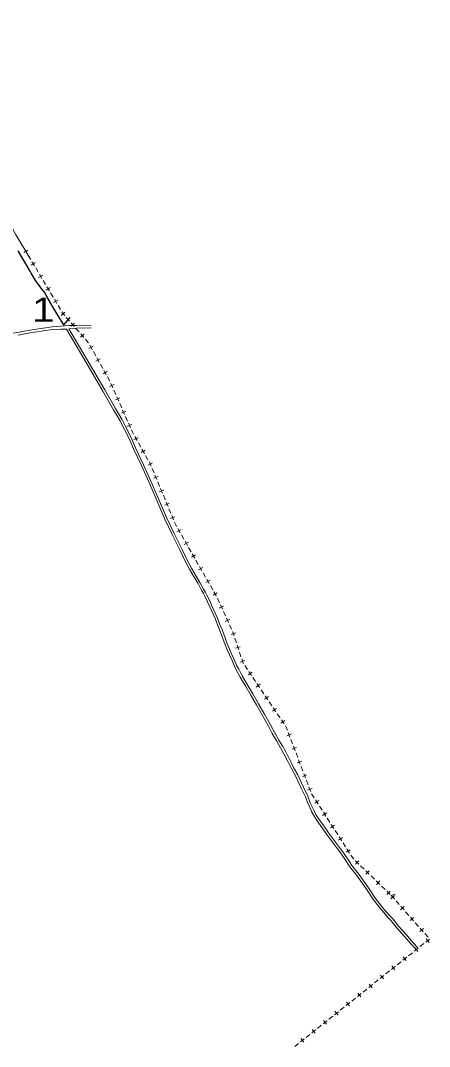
# Model space of a CAD drawing. Extents: x 476989 to 498418, y 4381813 to 4416555.
# Drawn here: x 487660 to 488503, y 4383749 to 4385862 of the extents above; entities that cross this region are included whole.
import ezdxf

# ---------------------------------------------------------------- set-up
doc = ezdxf.new("R2010")
doc.units = 0
doc.header["$LTSCALE"] = 20
for name, color, linetype, lineweight in [('13', 7, 'Continuous', 13), ('34', 7, 'Continuous', 13), ('36', 7, 'Continuous', 13), ('6', 7, 'Continuous', 25)]:
    doc.layers.add(name, color=color, linetype=linetype, lineweight=lineweight)

msp = doc.modelspace()

# ---------------------------------------------------------------- linework, layer by layer
at = {"layer": '34'}
for p, q in [((487660.88, 4385403.79), (487666.01, 4385395.21)), ((487675.43, 4385389.2), (487666.84, 4385384.07)), ((487668.57, 4385390.93), (487673.7, 4385382.34)), ((487676.26, 4385378.05), (487680.1, 4385371.63)), ((487680.1, 4385371.63), (487681.39, 4385369.47)), ((487690.81, 4385363.45), (487682.22, 4385358.33)), ((487683.95, 4385365.18), (487689.08, 4385356.6)), ((487691.65, 4385352.31), (487696.78, 4385343.72)), ((487706.19, 4385337.71), (487697.61, 4385332.58)), ((487699.34, 4385339.44), (487704.47, 4385330.85)), ((487707.03, 4385326.56), (487712.16, 4385317.98)), ((487721.58, 4385311.97), (487712.99, 4385306.84)), ((487714.72, 4385313.69), (487719.85, 4385305.11)), ((487722.41, 4385300.82), (487727.54, 4385292.23)), ((487730.1, 4385287.95), (487735.23, 4385279.37)), ((487736.96, 4385286.22), (487728.38, 4385281.09)), ((487737.8, 4385275.07), (487742.93, 4385266.49)), ((487751.82, 4385261.23), (487744.31, 4385254.62)), ((487754.68, 4385250.42), (487761.29, 4385242.92)), ((487771.65, 4385238.73), (487764.14, 4385232.12)), ((487764.59, 4385239.18), (487771.2, 4385231.68)), ((487774.51, 4385227.92), (487781.12, 4385220.42)), ((487791.48, 4385216.23), (487783.97, 4385209.62)), ((487784.42, 4385216.68), (487791.03, 4385209.18)), ((487809.92, 4385191.44), (487801.18, 4385186.58)), ((487803.12, 4385193.38), (487807.98, 4385184.64)), ((487810.4, 4385180.27), (487815.26, 4385171.53)), ((487824.48, 4385165.23), (487815.74, 4385160.37)), ((487817.68, 4385167.17), (487822.54, 4385158.43)), ((487824.97, 4385154.06), (487829.83, 4385145.31)), ((487832.25, 4385140.95), (487837.11, 4385132.21)), ((487839.05, 4385139.01), (487830.31, 4385134.15)), ((487839.53, 4385127.84), (487844.39, 4385119.1)), ((487853.11, 4385112.03), (487843.96, 4385107.99)), ((487846.51, 4385114.59), (487850.56, 4385105.44)), ((487852.58, 4385100.87), (487856.62, 4385091.72)), ((487865.24, 4385084.61), (487856.09, 4385080.56)), ((487858.64, 4385087.16), (487862.69, 4385078.01)), ((487864.71, 4385073.44), (487868.75, 4385064.29)), ((487877.37, 4385057.18), (487868.22, 4385053.14)), ((487870.77, 4385059.73), (487874.82, 4385050.59)), ((487876.84, 4385046.01), (487880.89, 4385036.87)), ((487889.5, 4385029.75), (487880.35, 4385025.71)), ((487882.9, 4385032.3), (487886.95, 4385023.16)), ((487902.68, 4385003.38), (487893.96, 4384998.49)), ((487895.88, 4385005.3), (487900.77, 4384996.58)), ((487903.21, 4384992.21), (487908.1, 4384983.49)), ((487917.35, 4384977.22), (487908.63, 4384972.33)), ((487910.54, 4384979.14), (487915.43, 4384970.42)), ((487917.88, 4384966.06), (487922.77, 4384957.33)), ((487932.01, 4384951.06), (487923.29, 4384946.17)), ((487931.57, 4384939.42), (487935.41, 4384930.19)), ((487943.86, 4384922.89), (487934.63, 4384919.04)), ((487937.33, 4384925.58), (487941.17, 4384916.35)), ((487943.09, 4384911.73), (487946.93, 4384902.5)), ((487955.38, 4384895.2), (487946.15, 4384891.35)), ((487948.85, 4384897.89), (487952.69, 4384888.66)), ((487954.61, 4384884.04), (487958.45, 4384874.81)), ((487966.9, 4384867.51), (487957.67, 4384863.66)), ((487960.36, 4384870.2), (487964.2, 4384860.97)), ((487966.13, 4384856.35), (487969.97, 4384847.12)), ((487978.42, 4384839.82), (487969.19, 4384835.98)), ((487971.88, 4384842.51), (487975.72, 4384833.28)), ((487991.22, 4384813.46), (487982.54, 4384808.49)), ((487984.4, 4384815.31), (487989.37, 4384806.63)), ((487991.85, 4384802.3), (487996.82, 4384793.62)), ((488006.12, 4384787.43), (487997.44, 4384782.46)), ((487999.3, 4384789.29), (488004.27, 4384780.61)), ((488006.75, 4384776.27), (488011.72, 4384767.59)), ((488021.02, 4384761.4), (488012.34, 4384756.44)), ((488014.2, 4384763.26), (488019.16, 4384754.58)), ((488021.65, 4384750.24), (488026.62, 4384741.56)), ((488035.92, 4384735.38), (488027.24, 4384730.41)), ((488029.1, 4384737.23), (488034.06, 4384728.55)), ((488036.55, 4384724.21), (488041.52, 4384715.53)), ((488050.82, 4384709.35), (488042.14, 4384704.38)), ((488043.99, 4384711.2), (488048.96, 4384702.52)), ((488051.45, 4384698.19), (488056.41, 4384689.51)), ((488065.72, 4384683.32), (488057.04, 4384678.35)), ((488065.82, 4384671.89), (488070, 4384662.8)), ((488078.72, 4384655.82), (488069.64, 4384651.64)), ((488072.09, 4384658.27), (488076.27, 4384649.19)), ((488078.36, 4384644.65), (488082.54, 4384635.56)), ((488091.26, 4384628.58), (488082.18, 4384624.4)), ((488084.63, 4384631.03), (488088.81, 4384621.95)), ((488090.91, 4384617.4), (488095.09, 4384608.32)), ((488103.7, 4384600.68), (488094.19, 4384597.56)), ((488102.06, 4384589.62), (488105.18, 4384580.12)), ((488113.05, 4384572.18), (488103.54, 4384569.07)), ((488106.74, 4384575.38), (488109.85, 4384565.88)), ((488111.41, 4384561.12), (488114.53, 4384551.62)), ((488122.4, 4384543.69), (488112.89, 4384540.57)), ((488122.17, 4384533.32), (488127.77, 4384525.04)), ((488137.51, 4384519.57), (488129.23, 4384513.96)), ((488130.57, 4384520.91), (488136.18, 4384512.62)), ((488138.98, 4384508.48), (488144.59, 4384500.2)), ((488154.33, 4384494.73), (488146.05, 4384489.13)), ((488147.38, 4384496.07), (488152.99, 4384487.79)), ((488155.79, 4384483.65), (488161.4, 4384475.37)), ((488171.14, 4384469.9), (488162.86, 4384464.29)), ((488164.19, 4384471.24), (488169.8, 4384462.95)), ((488172.6, 4384458.81), (488178.21, 4384450.53)), ((488187.95, 4384445.06), (488179.67, 4384439.46)), ((488181.01, 4384446.4), (488186.61, 4384438.12)), ((488189.41, 4384433.98), (488195.02, 4384425.7)), ((488197.82, 4384421.57), (488203.42, 4384413.28)), ((488204.76, 4384420.23), (488196.48, 4384414.62)), ((488218.3, 4384392.39), (488208.96, 4384388.83)), ((488211.85, 4384395.28), (488215.41, 4384385.94)), ((488217.19, 4384381.27), (488220.76, 4384371.92)), ((488228.99, 4384364.37), (488219.64, 4384360.81)), ((488222.53, 4384367.26), (488226.1, 4384357.92)), ((488227.88, 4384353.25), (488231.44, 4384343.9)), ((488239.67, 4384336.35), (488230.33, 4384332.79)), ((488233.22, 4384339.24), (488236.78, 4384329.9)), ((488238.56, 4384325.22), (488242.12, 4384315.88)), ((488250.36, 4384308.33), (488241.01, 4384304.76)), ((488243.9, 4384311.22), (488247.47, 4384301.87)), ((488249.25, 4384297.2), (488252.81, 4384287.86)), ((488261.04, 4384280.31), (488251.7, 4384276.74)), ((488254.59, 4384283.2), (488258.15, 4384273.85)), ((488274.9, 4384255.04), (488266.48, 4384249.64)), ((488267.99, 4384256.55), (488273.39, 4384248.13)), ((488276.09, 4384243.92), (488281.5, 4384235.51)), ((488284.19, 4384231.31), (488289.59, 4384222.89)), ((488291.1, 4384229.8), (488282.68, 4384224.4)), ((488292.29, 4384218.68), (488297.69, 4384210.27)), ((488307.3, 4384204.56), (488298.88, 4384199.16)), ((488300.39, 4384206.07), (488305.79, 4384197.65)), ((488308.49, 4384193.44), (488313.89, 4384185.03)), ((488323.5, 4384179.32), (488315.08, 4384173.92)), ((488316.59, 4384180.83), (488321.99, 4384172.41)), ((488324.69, 4384168.21), (488330.09, 4384159.79)), ((488339.69, 4384154.08), (488331.28, 4384148.68)), ((488332.79, 4384155.59), (488338.19, 4384147.17)), ((488349.98, 4384131.17), (488353.26, 4384128.02)), ((488353.89, 4384128.02), (488350.12, 4384124.1)), ((488353.26, 4384128.02), (488357.19, 4384124.24)), ((488357.05, 4384131.31), (488353.89, 4384128.02)), ((488360.79, 4384120.77), (488368, 4384113.84)), ((488371.6, 4384110.38), (488378.81, 4384103.45)), ((488378.67, 4384110.52), (488371.74, 4384103.32)), ((488382.41, 4384099.99), (488389.62, 4384093.06)), ((488393.22, 4384089.6), (488400.43, 4384082.67)), ((488400.29, 4384089.74), (488393.36, 4384082.53)), ((488404.03, 4384079.2), (488411.24, 4384072.27)), ((488414.84, 4384068.81), (488422.04, 4384061.88)), ((488421.9, 4384068.95), (488414.97, 4384061.74)), ((488432.07, 4384062.39), (488424, 4384060)), ((488431.05, 4384059.55), (488423.53, 4384052.95)), ((488424, 4384060), (488430.59, 4384052.49)), ((488433.89, 4384048.73), (488440.49, 4384041.22)), ((488450.83, 4384037.01), (488443.32, 4384030.41)), ((488443.78, 4384037.47), (488450.37, 4384029.95)), ((488453.67, 4384026.2), (488460.27, 4384018.68)), ((488470.62, 4384014.47), (488463.1, 4384007.87)), ((488463.56, 4384014.93), (488470.16, 4384007.41)), ((488473.46, 4384003.66), (488480.05, 4383996.14)), ((488490.4, 4383991.93), (488482.89, 4383985.34)), ((488483.35, 4383992.39), (488489.94, 4383984.88)), ((488493.24, 4383981.12), (488499.84, 4383973.6)), ((488491.12, 4383960.53), (488483.3, 4383954.3)), ((488502.85, 4383969.88), (488495.03, 4383963.65)), ((488502.05, 4383962.85), (488495.82, 4383970.67)), ((488467.66, 4383941.84), (488459.84, 4383935.61)), ((488479.39, 4383951.19), (488471.57, 4383944.95)), ((488478.6, 4383944.16), (488472.37, 4383951.98)), ((488432.49, 4383913.8), (488424.67, 4383907.57)), ((488431.69, 4383906.78), (488425.46, 4383914.6)), ((488444.21, 4383923.15), (488436.39, 4383916.91)), ((488455.94, 4383932.5), (488448.12, 4383926.26)), ((488455.15, 4383925.47), (488448.91, 4383933.29)), ((488409.04, 4383895.11), (488401.22, 4383888.88)), ((488408.24, 4383888.09), (488402.01, 4383895.91)), ((488420.76, 4383904.46), (488412.94, 4383898.22)), ((488385.58, 4383876.42), (488377.76, 4383870.19)), ((488384.79, 4383869.39), (488378.56, 4383877.21)), ((488397.31, 4383885.76), (488389.48, 4383879.53)), ((488362.13, 4383857.73), (488354.31, 4383851.5)), ((488361.34, 4383850.7), (488355.1, 4383858.52)), ((488373.85, 4383867.07), (488366.03, 4383860.84)), ((488326.95, 4383829.69), (488319.13, 4383823.46)), ((488338.68, 4383839.04), (488330.86, 4383832.81)), ((488337.88, 4383832.01), (488331.65, 4383839.83)), ((488350.4, 4383848.38), (488342.58, 4383842.15)), ((488303.49, 4383811), (488295.67, 4383804.77)), ((488315.22, 4383820.35), (488307.4, 4383814.11)), ((488314.43, 4383813.32), (488308.2, 4383821.14)), ((488280.04, 4383792.31), (488272.22, 4383786.07)), ((488291.77, 4383801.66), (488283.95, 4383795.42)), ((488290.98, 4383794.63), (488284.75, 4383802.45)), ((488256.59, 4383773.62), (488248.77, 4383767.38)), ((488268.32, 4383782.96), (488260.5, 4383776.73)), ((488267.52, 4383775.94), (488261.29, 4383783.76)), ((488233.14, 4383754.92), (488225.32, 4383748.69)), ((488244.87, 4383764.27), (488237.05, 4383758.04)), ((488244.07, 4383757.25), (488237.84, 4383765.07))]:
    msp.add_line(p, q, dxfattribs=at)
for points in [[(487280.6, 4386441.97), (487080, 4386339), (487267, 4386051), (487354, 4385933), (487441, 4385795), (487598, 4385523), (487650, 4385422), (487680.1, 4385371.64)], [(487745.49, 4385262.21), (487748, 4385258), (487751.37, 4385254.17)], [(487794.34, 4385205.43), (487800, 4385199), (487800.7, 4385197.75)], [(487888.97, 4385018.59), (487891, 4385014), (487893.44, 4385009.65)], [(487925.21, 4384952.98), (487928, 4384948), (487929.65, 4384944.04)], [(487977.64, 4384828.66), (487980, 4384823), (487981.92, 4384819.64)], [(488058.89, 4384685.18), (488063, 4384678), (488063.72, 4384676.43)], [(488097.18, 4384603.79), (488098, 4384602), (488100.5, 4384594.37)], [(488116.09, 4384546.88), (488119, 4384538), (488119.37, 4384537.46)], [(488206.23, 4384409.14), (488207, 4384408), (488210.07, 4384399.95)], [(488259.93, 4384269.18), (488260, 4384269), (488265.3, 4384260.75)], [(488340.89, 4384142.97), (488346, 4384135), (488346.38, 4384134.63)]]:
    msp.add_lwpolyline(points, dxfattribs=at)
at = {"layer": '36'}
for p, q in [((487679.81, 4385224.07), (487679.85, 4385224.08)), ((487679.8, 4385218.38), (487679.84, 4385218.39)), ((488332.78, 4384128.05), (488333.4, 4384127.12)), ((488338.74, 4384128.04), (488339.36, 4384127.11))]:
    msp.add_line(p, q, dxfattribs=at)
for points in [[(487497.15, 4385199.42), (487509.69, 4385199.56), (487530.73, 4385201.64), (487543.2, 4385202.51), (487556.97, 4385203.85), (487571.79, 4385206.52), (487597.97, 4385211.35), (487621.23, 4385214.93), (487654.34, 4385219.7), (487679.81, 4385224.07)], [(487679.84, 4385218.39), (487689.06, 4385219.97), (487725.96, 4385225.31), (487743.45, 4385226.24), (487754.77, 4385226.5)], [(487679.85, 4385224.08), (487688.19, 4385225.51), (487725.41, 4385230.89), (487751.05, 4385232.88)], [(487751.51, 4385233.11), (487760.04, 4385233.57), (487775.61, 4385233.93), (487805.83, 4385234.71)], [(487754.77, 4385226.5), (487795.93, 4385157.57), (487829.92, 4385098.83), (487852.21, 4385060.31)], [(487760.04, 4385226.64), (487775.98, 4385228.34), (487805.98, 4385229.09)], [(487760.04, 4385226.64), (487799.89, 4385159.9), (487833.9, 4385101.14), (487856.19, 4385062.62)], [(487655.21, 4385214.16), (487679.8, 4385218.38)], [(487852.21, 4385060.31), (487865.52, 4385037.09), (487871.17, 4385026.06), (487877.83, 4385013.17), (487885.41, 4384997.67), (487892.78, 4384980.04), (487909.58, 4384945.08), (487927.48, 4384905.25), (487957.67, 4384834.81), (487972.51, 4384803.57), (487989.09, 4384770.37), (488000.47, 4384746.72), (488008.53, 4384731.68), (488017.92, 4384715.2), (488026.08, 4384702.24), (488033.4, 4384688.72), (488037.26, 4384681.81), (488039.95, 4384676.45), (488045.87, 4384664.41), (488050.54, 4384654.49), (488054.62, 4384645.57), (488057.39, 4384639.08), (488062.05, 4384628.97), (488066.76, 4384615.91), (488071.16, 4384605.55), (488074.65, 4384596.59), (488077, 4384588.77)], [(487856.19, 4385062.62), (487869.5, 4385039.41), (487875.26, 4385028.16), (487881.94, 4385015.24), (487889.6, 4384999.57), (487896.98, 4384981.93), (487913.76, 4384947.02), (487931.69, 4384907.09), (487961.86, 4384836.7), (487976.64, 4384805.58), (487993.22, 4384772.4), (488004.57, 4384748.81), (488012.55, 4384733.91), (488021.87, 4384717.57), (488030.06, 4384704.56), (488037.43, 4384690.93), (488041.33, 4384683.96), (488044.07, 4384678.49), (488050.02, 4384666.41), (488054.72, 4384656.43), (488058.83, 4384647.43), (488061.6, 4384640.95), (488066.31, 4384630.72), (488071.05, 4384617.59), (488075.42, 4384607.28), (488078.92, 4384598.31), (488081.65, 4384590.5)], [(488081.65, 4384590.5), (488086.37, 4384577.81), (488090.65, 4384567.62), (488095.25, 4384557.47), (488100.6, 4384545.98), (488105.56, 4384534.32), (488109.92, 4384525.64), (488117.24, 4384512.11), (488128.55, 4384492.58), (488139.09, 4384474.89), (488150.57, 4384454.8), (488162.92, 4384432.9), (488175.67, 4384411.04), (488183.45, 4384396.02), (488192.62, 4384379.97), (488200.42, 4384366.3), (488207.44, 4384354.1), (488214.28, 4384340.4), (488219.04, 4384330.9), (488222.99, 4384323.32), (488231.38, 4384308.11), (488243.29, 4384283.17), (488252.18, 4384264.54), (488257.14, 4384250.9), (488261.27, 4384242.16), (488265.21, 4384233.89), (488268.91, 4384226.73), (488275.32, 4384216.42), (488285.7, 4384202.17), (488294.93, 4384189.09), (488309.18, 4384169.66), (488325.75, 4384147.54), (488338.74, 4384128.04)], [(488077, 4384588.77), (488081.75, 4384575.98), (488086.1, 4384565.63), (488090.74, 4384555.4), (488096.06, 4384543.96), (488101.05, 4384532.24), (488105.52, 4384523.34), (488112.91, 4384509.68), (488124.28, 4384490.07), (488134.8, 4384472.39), (488146.25, 4384452.35), (488158.62, 4384430.43), (488171.32, 4384408.65), (488179.09, 4384393.64), (488188.32, 4384377.51), (488196.12, 4384363.84), (488203.07, 4384351.75), (488209.85, 4384338.18), (488214.63, 4384328.65), (488218.61, 4384320.97), (488226.97, 4384305.84), (488238.81, 4384281.03), (488247.6, 4384262.62), (488252.55, 4384248.99), (488256.79, 4384240.03), (488260.77, 4384231.68), (488264.59, 4384224.27), (488271.21, 4384213.65), (488281.67, 4384199.28), (488290.9, 4384186.19), (488305.19, 4384166.71), (488321.7, 4384144.67), (488332.78, 4384128.05)], [(488333.4, 4384127.12), (488338.92, 4384118.84), (488353.38, 4384100.94), (488373.15, 4384072.85), (488387.79, 4384050.88), (488400.24, 4384034.62), (488409.33, 4384023.73), (488416.52, 4384015.35), (488424.19, 4384007.74), (488435.14, 4383993.67), (488450.82, 4383975.8), (488465.89, 4383958.57), (488475.23, 4383948.42)], [(488339.36, 4384127.11), (488342.92, 4384121.78), (488357.34, 4384103.93), (488377.25, 4384075.65), (488391.83, 4384053.77), (488404.12, 4384037.72), (488413.11, 4384026.93), (488420.16, 4384018.74), (488427.91, 4384011.04), (488438.97, 4383996.84), (488454.55, 4383979.06), (488469.58, 4383961.88), (488479.08, 4383951.57)]]:
    msp.add_lwpolyline(points, dxfattribs=at)
at = {"layer": '6'}
msp.add_line((487750.16, 4385235.72), (487762.56, 4385250.47), dxfattribs=at)
for points in [[(487680, 4385345.5), (487666.97, 4385367.8), (487655.53, 4385387.66)], [(487750.13, 4385234.72), (487744.74, 4385242.95), (487729.34, 4385267.75), (487714.67, 4385293.38), (487709.58, 4385302.34), (487705.22, 4385308.13), (487701.54, 4385312.54), (487696.47, 4385319.22), (487690.86, 4385327.71), (487682.31, 4385341.56), (487680.05, 4385345.41)]]:
    msp.add_lwpolyline(points, dxfattribs=at)

# ---------------------------------------------------------------- texts
at = {"layer": '13', "width": 1.25}
msp.add_text('1', height=50, dxfattribs=at).set_placement((487684.03, 4385241.38))

doc.saveas('drawing.dxf')
